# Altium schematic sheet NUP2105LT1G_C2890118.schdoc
size 127 x 101 mm
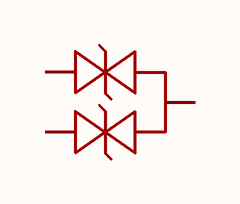
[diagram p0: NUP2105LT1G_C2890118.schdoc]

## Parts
D?  nup2105lt1g_c2890118  [SOT-23-3_L2.9-W1.3-P1.90-LS2.4-BR]  (value not drawn)

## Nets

Not connected (* = marked no-connect by the designer): D? 1(C) 2(C) 3(A)

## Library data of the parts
D? = nup2105lt1g_c2890118: 极性:双向;反向截止电压(Vrwm):24V;钳位电压:43V;峰值脉冲电流(Ipp):7A;峰值脉冲功率(Ppp):300W@8/20us;击穿电压:26.7V;; Manufacturer: TECH PUBLIC(台舟); AddInBom: yes; ModelId: c62791f0466c4ae2a892c056b845b0ca; ModelName: SOT-23-3P_L2.9-W1.3-H1.0-LS2.4-P0.95; ModelTransform: 98.425,114.173,0,180,0,0,0.0005,-0.0005,0; Polarity: 双向; Reverse Stand-Off Voltage (Vrwm): 24V; Clamping Voltage: 43V; Peak Pulse Current (Ipp): 7A; Voltage - Breakdown: 26.7V; Reverse Leakage Current (Ir): 80nA; Number of Channels: 双路; level of protection: IEC 61000-4-2；IEC 61000-4-4; Type: ESD; Junction Capacitance: 25pF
